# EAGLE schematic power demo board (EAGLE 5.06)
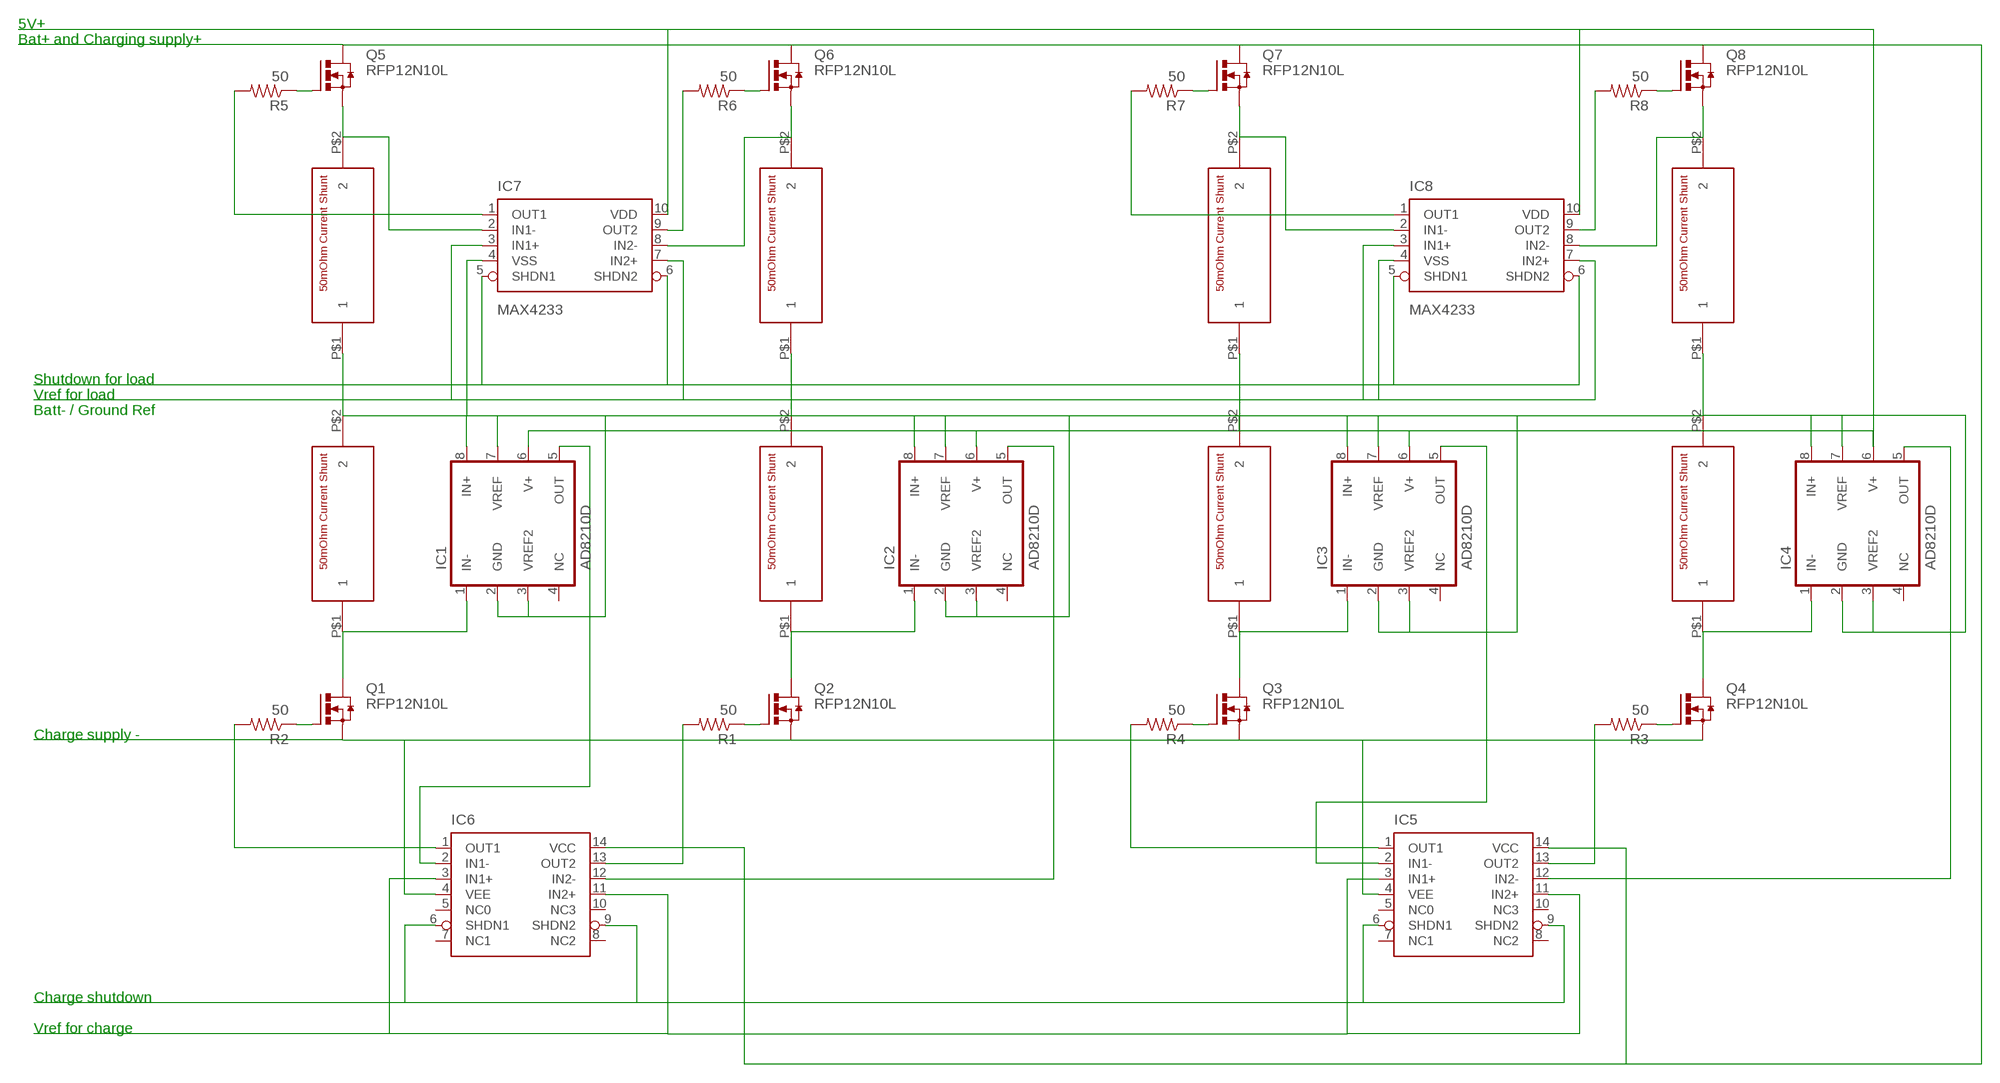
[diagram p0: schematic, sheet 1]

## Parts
IC1  AD8210D  [SO08]
IC2  AD8210D  [SO08]
IC3  AD8210D  [SO08]
IC4  AD8210D  [SO08]
IC5  MAX4168D  [SO14]
IC6  MAX4168D  [SO14]
IC7  MAX4233  [UMAX10]
IC8  MAX4233  [UMAX10]
Q1  RFP12N10L  [TO220-W/657-20ABP]
Q2  RFP12N10L  [TO220-W/657-20ABP]
Q3  RFP12N10L  [TO220-W/657-20ABP]
Q4  RFP12N10L  [TO220-W/657-20ABP]
Q5  RFP12N10L  [TO220-W/657-20ABP]
Q6  RFP12N10L  [TO220-W/657-20ABP]
Q7  RFP12N10L  [TO220-W/657-20ABP]
Q8  RFP12N10L  [TO220-W/657-20ABP]
R1  50  R-US_0207/10  [0207/10]
R2  50  R-US_0207/10  [0207/10]
R3  50  R-US_0207/10  [0207/10]
R4  50  R-US_0207/10  [0207/10]
R5  50  R-US_0207/10  [0207/10]
R6  50  R-US_0207/10  [0207/10]
R7  50  R-US_0207/10  [0207/10]
R8  50  R-US_0207/10  [0207/10]
U$1  630HR050E  [630HR050E]
U$2  630HR050E  [630HR050E]
U$3  630HR050E  [630HR050E]
U$4  630HR050E  [630HR050E]
U$5  630HR050E  [630HR050E]
U$6  630HR050E  [630HR050E]
U$7  630HR050E  [630HR050E]
U$8  630HR050E  [630HR050E]

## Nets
N$1: IC5.13(OUT2) R3.2
N$2: IC1.1(IN-) Q1.2(D) U$5.P$1
N$3: IC2.1(IN-) Q2.2(D) U$6.P$1
N$4: IC3.1(IN-) Q3.2(D) U$7.P$1
N$5: IC7.3(IN1+) IC7.7(IN2+) IC8.3(IN1+) IC8.4(VSS) IC8.7(IN2+)
N$6: IC5.4(VEE) IC6.4(VEE) Q1.3(S) Q2.3(S) Q3.3(S) Q4.3(S)
N$7: IC7.2(IN1-) Q5.3(S) U$1.P$2
N$8: IC7.8(IN2-) Q6.3(S) U$2.P$2
N$9: IC8.2(IN1-) Q7.3(S) U$3.P$2
N$10: IC8.8(IN2-) Q8.3(S) U$4.P$2
N$11: IC5.14(VCC) IC6.14(VCC) Q5.2(D) Q6.2(D) Q7.2(D) Q8.2(D)
N$12: IC7.1(OUT1) R5.2
N$13: Q5.1(G) R5.1
N$14: IC7.9(OUT2) R6.2
N$15: Q6.1(G) R6.1
N$16: Q7.1(G) R7.1
N$17: IC8.1(OUT1) R7.2
N$18: Q8.1(G) R8.1
N$19: IC8.9(OUT2) R8.2
N$20: IC7.5(SHDN1) IC7.6(SHDN2) IC8.5(SHDN1) IC8.6(SHDN2)
N$21: IC4.1(IN-) Q4.2(D) U$8.P$1
N$22: IC5.6(SHDN1) IC5.9(SHDN2) IC6.6(SHDN1) IC6.9(SHDN2)
N$23: IC6.13(OUT2) R1.2
N$24: Q1.1(G) R2.1
N$25: Q2.1(G) R1.1
N$26: Q3.1(G) R4.1
N$27: Q4.1(G) R3.1
N$28: IC5.1(OUT1) R4.2
N$29: IC2.5(OUT) IC6.12(IN2-)
N$31: IC5.3(IN1+) IC5.11(IN2+) IC6.3(IN1+) IC6.11(IN2+)
N$32: IC1.5(OUT) IC6.2(IN1-)
N$33: IC6.1(OUT1) R2.2
N$34: IC4.5(OUT) IC5.12(IN2-)
N$35: IC3.5(OUT) IC5.2(IN1-)
N$36: IC1.2(GND) IC1.3(VREF2) IC1.7(VREF) IC1.8(IN+) IC2.2(GND) IC2.3(VREF2) IC2.7(VREF) IC2.8(IN+) IC3.2(GND) IC3.3(VREF2) IC3.7(VREF) IC3.8(IN+) IC4.2(GND) IC4.3(VREF2) IC4.7(VREF) IC4.8(IN+) IC7.4(VSS) U$1.P$1 U$2.P$1 U$3.P$1 U$4.P$1 U$5.P$2 U$6.P$2 U$7.P$2 U$8.P$2
N$40: IC1.6(V+) IC2.6(V+) IC3.6(V+) IC4.6(V+) IC7.10(VDD) IC8.10(VDD)
Unconnected: IC5.5(NC0) IC5.7(NC1) IC5.10(NC3) IC6.5(NC0) IC6.7(NC1) IC6.10(NC3)

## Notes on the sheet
- 5V+
- Bat+ and Charging supply+
- Shutdown for load
- Vref for load
- Batt- / Ground Ref
- Charge supply -
- Charge shutdown
- Vref for charge

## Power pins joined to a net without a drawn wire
NC: IC1.4(NC) IC2.4(NC) IC3.4(NC) IC4.4(NC)
NC2: IC5.8(NC2) IC6.8(NC2)

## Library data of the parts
IC1-IC4 = NEWPARTS:AD8210: High Voltage, Bidirectional Current Shunt Monitor
IC5 IC6 = NEWPARTS:MAX4168: High-Output-Drive, Precision, Low-power, Single-Supply, Rail-to-Rail I/O Op Amps with Shutdown
IC7 IC8 = NEWPARTS:MAX4233: High-Output-Drive, 10MHz, 10V/us, Rail-to_rail I/O Op Amps with Shutdown in SC70
Q1-Q8 = NEWPARTS:RFP12N10L: N-Channel Power MOSFET 100V; 12A; 0,2Ohm< Logic Level
R1-R8 = rcl:R-US_: RESISTOR, American symbol
U$1-U$8 = NEWPARTS:630HR050E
